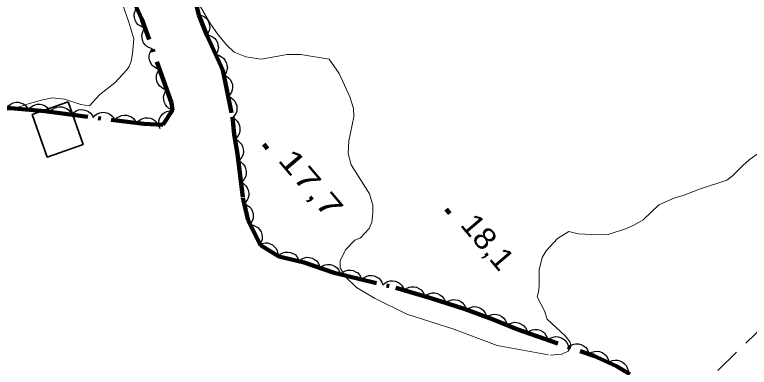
# Model space of a CAD drawing. Extents: x 386081 to 389416, y 5130568 to 5134082.
# Drawn here: x 387832.9 to 387934.2, y 5132350.3 to 5132398.8 of the extents above; entities that cross this region are included whole.
import ezdxf

# ---------------------------------------------------------------- set-up
doc = ezdxf.new("R2010")
doc.units = 0
doc.header["$LTSCALE"] = 1.2
for name, pattern in [('DOT_DASHED', [7.7, 5, -1.2, 0.3, -1.2]), ('LONG_DASHED', [7.5, 6, -1.5]), ('MEDIUM_DASHED', [4.5, 3, -1.5])]:
    doc.linetypes.add(name, pattern=pattern)
for name, color, linetype, lineweight in [('2', 7, 'Continuous', 13), ('21', 7, 'LONG_DASHED', 35), ('3', 7, 'Continuous', 140), ('31', 7, 'Continuous', 70), ('44', 7, 'Continuous', 25)]:
    doc.layers.add(name, color=color, linetype=linetype, lineweight=lineweight)

msp = doc.modelspace()

# ---------------------------------------------------------------- linework, layer by layer
at = {"layer": '2', "linetype": 'LONG_DASHED'}
for points in [[(387851.7, 5132416.27), (387848.9, 5132422.14), (387847.79, 5132425.35), (387846.86, 5132427.14), (387844.75, 5132429.85), (387843.63, 5132430.34), (387842.82, 5132429.9), (387842.32, 5132429.03), (387842.19, 5132427.54), (387842.37, 5132425.37), (387843.73, 5132419.43), (387845.59, 5132412.5), (387846.82, 5132404.45), (387847.74, 5132400.3), (387848.61, 5132397.83), (387849.29, 5132395.54), (387849.1, 5132393.49), (387848.91, 5132392.43), (387848.66, 5132391.69), (387848.35, 5132391.25)], [(387879.75, 5132367.77), (387878.5, 5132366.46), (387877.75, 5132364.96), (387877.75, 5132363.97), (387878.49, 5132362.74), (387879.98, 5132361.26), (387882.47, 5132359.8), (387886.95, 5132357.6), (387893.28, 5132355.56), (387899.37, 5132353.26), (387906.7, 5132351.96), (387908.32, 5132352.1), (387909.19, 5132352.48), (387909.56, 5132353.1), (387909.44, 5132353.72), (387908.82, 5132354.58), (387906.28, 5132356.91)]]:
    msp.add_lwpolyline(points, dxfattribs=at)
at = {"layer": '2'}
for points in [[(387879.75, 5132367.77), (387880.56, 5132368.09), (387881.74, 5132369.4), (387882.11, 5132370.27), (387882.24, 5132371.51), (387882.24, 5132372.63), (387881.81, 5132374.17), (387879.26, 5132378.18), (387878.83, 5132379.73), (387878.96, 5132381.46), (387879.65, 5132384.76), (387879.59, 5132385.93), (387879.09, 5132387.54), (387877.6, 5132390.75), (387876.24, 5132392.72), (387872.32, 5132393.37), (387870.45, 5132393.36), (387866.84, 5132392.71), (387864.73, 5132393.06), (387863.11, 5132393.67), (387862.12, 5132394.65), (387860.94, 5132396.07), (387859.76, 5132397.73), (387858.14, 5132400.57)], [(387848.35, 5132391.25), (387846.67, 5132389.44), (387844.61, 5132387.87), (387843.17, 5132386.31), (387841.99, 5132386.48), (387839.75, 5132387.21), (387838.06, 5132387.38), (387836.51, 5132387.06), (387834.45, 5132386.48), (387832.2, 5132385.72), (387831.14, 5132385.65), (387827.78, 5132386.61), (387823.73, 5132387.01), (387820.67, 5132387.05), (387817.8, 5132386.53), (387813.37, 5132385.43), (387809.87, 5132385.65), (387807.94, 5132385.95), (387805.94, 5132386.67), (387804.7, 5132387.41), (387803.14, 5132388.82), (387799.57, 5132393.79)], [(387936.17, 5132380.28), (387934.12, 5132378.84), (387933.25, 5132378.09), (387931.82, 5132376.65), (387931.07, 5132376.03), (387927.29, 5132374.82), (387925.05, 5132373.93), (387923.87, 5132373.61), (387921.7, 5132372.66), (387919.52, 5132370.6), (387918.34, 5132369.91), (387917.22, 5132369.4), (387914.68, 5132368.58), (387913.25, 5132368.5), (387910.58, 5132368.66), (387909.27, 5132368.96), (387907.72, 5132368.02), (387906.16, 5132366.33), (387905.6, 5132365.4), (387905.17, 5132363.72), (387905.16, 5132361.49), (387905.1, 5132360.68), (387904.91, 5132360), (387905.9, 5132358.03), (387906.28, 5132356.91)]]:
    msp.add_lwpolyline(points, dxfattribs=at)
at = {"layer": '21', "linetype": 'MEDIUM_DASHED'}
msp.add_lwpolyline([(387860.78, 5132286.44), (387862.78, 5132287.28), (387865.84, 5132288.2), (387868.86, 5132289.23), (387870.95, 5132290.29), (387873.09, 5132291.74), (387875.38, 5132293.66), (387881.62, 5132300.01), (387887.6, 5132305.78), (387894.9, 5132314.12), (387902.8, 5132322.8), (387912.7, 5132332.94), (387922.03, 5132342.34), (387944.62, 5132364.16), (387960.02, 5132379.36), (387967.89, 5132387.55), (387974.37, 5132394.99), (387979.87, 5132401.66), (387990.47, 5132414.87), (387993.62, 5132418.08), (388000.82, 5132427.01), (388006.82, 5132435.09), (388017.51, 5132449)], dxfattribs=at)
at = {"layer": '3'}
for p, q in [((387867.21, 5132381), (387867.72, 5132380.39)), ((387892.35, 5132372.08), (387892.86, 5132371.47))]:
    msp.add_line(p, q, dxfattribs=at)
at = {"layer": '31', "lineweight": 35}
msp.add_lwpolyline([(387840.24, 5132386.83), (387835.29, 5132385.09), (387837.34, 5132379.23), (387842.29, 5132380.96)], close=True, dxfattribs=at)
at = {"layer": '44', "linetype": 'DOT_DASHED', "lineweight": 90}
for points in [[(387831.29, 5132386.07), (387837.01, 5132385.55), (387850.69, 5132383.79), (387853.3, 5132383.66), (387854.61, 5132385.7), (387854.48, 5132386.7), (387850.42, 5132398.21), (387848.66, 5132402.09)], [(387857.55, 5132401.7), (387858.28, 5132398.8), (387859.37, 5132396.02), (387861.55, 5132391.19), (387862.88, 5132384.77), (387863.12, 5132382.35), (387863.6, 5132379.68), (387864.33, 5132373.63), (387865.06, 5132370.48), (387866.75, 5132367.1), (387869.29, 5132365.55), (387872.8, 5132364.73), (387876.92, 5132363.31), (387885.4, 5132361.21), (387890.24, 5132359.79), (387894.96, 5132358.26), (387898.83, 5132356.84), (387902.1, 5132355.54), (387912.71, 5132351.85), (387915.86, 5132350.42), (387917.67, 5132349.35)]]:
    msp.add_lwpolyline(points, dxfattribs=at)
at = {"layer": '44'}
for points in [[(387850.95, 5132397.03), (387850.54, 5132397.1), (387850.18, 5132397.29), (387849.91, 5132397.47), (387849.68, 5132397.74), (387849.5, 5132398.07), (387849.4, 5132398.44), (387849.35, 5132398.76), (387849.41, 5132399.11), (387849.53, 5132399.46), (387849.71, 5132399.77)], [(387858.26, 5132398.84), (387858.67, 5132398.75), (387859.02, 5132398.55), (387859.29, 5132398.35), (387859.49, 5132398.07), (387859.66, 5132397.74), (387859.74, 5132397.36), (387859.77, 5132397.04), (387859.7, 5132396.69), (387859.56, 5132396.35), (387859.36, 5132396.05)], [(387851.85, 5132394.16), (387851.44, 5132394.27), (387851.1, 5132394.48), (387850.84, 5132394.69), (387850.64, 5132394.98), (387850.49, 5132395.32), (387850.43, 5132395.69), (387850.4, 5132396.02), (387850.49, 5132396.36), (387850.64, 5132396.7), (387850.85, 5132396.99)], [(387859.36, 5132396.05), (387859.77, 5132395.98), (387860.13, 5132395.8), (387860.4, 5132395.61), (387860.63, 5132395.34), (387860.81, 5132395.02), (387860.9, 5132394.64), (387860.95, 5132394.32), (387860.9, 5132393.97), (387860.78, 5132393.62), (387860.59, 5132393.32)], [(387852.85, 5132391.33), (387852.44, 5132391.44), (387852.1, 5132391.65), (387851.84, 5132391.86), (387851.64, 5132392.15), (387851.49, 5132392.49), (387851.42, 5132392.86), (387851.4, 5132393.19), (387851.49, 5132393.53), (387851.63, 5132393.87), (387851.85, 5132394.16)], [(387860.59, 5132393.32), (387861, 5132393.25), (387861.37, 5132393.06), (387861.64, 5132392.88), (387861.86, 5132392.6), (387862.04, 5132392.28), (387862.14, 5132391.91), (387862.19, 5132391.59), (387862.13, 5132391.24), (387862.01, 5132390.89), (387861.82, 5132390.58)], [(387853.84, 5132388.5), (387853.44, 5132388.61), (387853.09, 5132388.82), (387852.84, 5132389.03), (387852.64, 5132389.32), (387852.49, 5132389.66), (387852.42, 5132390.04), (387852.4, 5132390.36), (387852.48, 5132390.7), (387852.63, 5132391.04), (387852.85, 5132391.33)], [(387861.69, 5132390.54), (387862.07, 5132390.38), (387862.39, 5132390.12), (387862.61, 5132389.88), (387862.77, 5132389.56), (387862.88, 5132389.21), (387862.89, 5132388.83), (387862.87, 5132388.5), (387862.74, 5132388.17), (387862.54, 5132387.86), (387862.29, 5132387.6)], [(387854.84, 5132385.67), (387854.44, 5132385.78), (387854.09, 5132385.99), (387853.84, 5132386.2), (387853.64, 5132386.49), (387853.48, 5132386.83), (387853.42, 5132387.21), (387853.4, 5132387.53), (387853.48, 5132387.87), (387853.63, 5132388.21), (387853.84, 5132388.5)], [(387862.29, 5132387.6), (387862.68, 5132387.44), (387862.99, 5132387.18), (387863.22, 5132386.94), (387863.38, 5132386.63), (387863.48, 5132386.27), (387863.5, 5132385.89), (387863.48, 5132385.56), (387863.34, 5132385.24), (387863.15, 5132384.92), (387862.9, 5132384.66)], [(387831.78, 5132386.03), (387832.05, 5132386.35), (387832.39, 5132386.57), (387832.68, 5132386.72), (387833.03, 5132386.78), (387833.4, 5132386.78), (387833.77, 5132386.68), (387834.07, 5132386.56), (387834.35, 5132386.34), (387834.6, 5132386.07), (387834.77, 5132385.75)], [(387834.77, 5132385.75), (387835.04, 5132386.08), (387835.37, 5132386.3), (387835.67, 5132386.45), (387836.02, 5132386.51), (387836.39, 5132386.51), (387836.76, 5132386.41), (387837.06, 5132386.29), (387837.34, 5132386.07), (387837.58, 5132385.8), (387837.76, 5132385.48)], [(387837.76, 5132385.45), (387838.03, 5132385.77), (387838.38, 5132385.98), (387838.68, 5132386.12), (387839.03, 5132386.16), (387839.4, 5132386.15), (387839.76, 5132386.03), (387840.06, 5132385.91), (387840.33, 5132385.68), (387840.57, 5132385.39), (387840.73, 5132385.07)], [(387840.73, 5132385.07), (387841.01, 5132385.38), (387841.35, 5132385.6), (387841.65, 5132385.73), (387842, 5132385.78), (387842.37, 5132385.76), (387842.74, 5132385.65), (387843.04, 5132385.52), (387843.31, 5132385.29), (387843.54, 5132385.01), (387843.71, 5132384.69)], [(387852.95, 5132383.11), (387852.78, 5132383.49), (387852.74, 5132383.9), (387852.74, 5132384.23), (387852.85, 5132384.56), (387853.02, 5132384.89), (387853.28, 5132385.17), (387853.53, 5132385.39), (387853.85, 5132385.53), (387854.21, 5132385.62), (387854.57, 5132385.63)], [(387843.71, 5132384.69), (387843.98, 5132385), (387844.33, 5132385.22), (387844.63, 5132385.35), (387844.98, 5132385.4), (387845.35, 5132385.38), (387845.71, 5132385.27), (387846.01, 5132385.14), (387846.28, 5132384.91), (387846.52, 5132384.63), (387846.68, 5132384.31)], [(387846.68, 5132384.31), (387846.96, 5132384.62), (387847.3, 5132384.83), (387847.61, 5132384.97), (387847.95, 5132385.01), (387848.32, 5132385), (387848.69, 5132384.89), (387848.99, 5132384.76), (387849.26, 5132384.53), (387849.49, 5132384.24), (387849.66, 5132383.92)], [(387849.65, 5132383.84), (387849.9, 5132384.18), (387850.23, 5132384.42), (387850.52, 5132384.57), (387850.86, 5132384.65), (387851.23, 5132384.66), (387851.61, 5132384.58), (387851.92, 5132384.47), (387852.2, 5132384.27), (387852.46, 5132384), (387852.65, 5132383.69)], [(387862.89, 5132384.66), (387863.26, 5132384.46), (387863.54, 5132384.17), (387863.74, 5132383.91), (387863.87, 5132383.58), (387863.93, 5132383.22), (387863.91, 5132382.83), (387863.85, 5132382.51), (387863.69, 5132382.2), (387863.46, 5132381.9), (387863.19, 5132381.67)], [(387863.24, 5132381.68), (387863.62, 5132381.51), (387863.93, 5132381.25), (387864.15, 5132381), (387864.3, 5132380.68), (387864.39, 5132380.32), (387864.4, 5132379.94), (387864.37, 5132379.62), (387864.23, 5132379.29), (387864.03, 5132378.98), (387863.77, 5132378.73)], [(387863.72, 5132378.72), (387864.09, 5132378.53), (387864.38, 5132378.25), (387864.58, 5132377.99), (387864.71, 5132377.66), (387864.79, 5132377.3), (387864.77, 5132376.92), (387864.72, 5132376.59), (387864.56, 5132376.28), (387864.35, 5132375.98), (387864.08, 5132375.74)], [(387864.08, 5132375.74), (387864.45, 5132375.55), (387864.74, 5132375.27), (387864.94, 5132375.01), (387865.07, 5132374.68), (387865.15, 5132374.32), (387865.13, 5132373.94), (387865.08, 5132373.62), (387864.92, 5132373.3), (387864.71, 5132373), (387864.43, 5132372.76)], [(387864.53, 5132372.78), (387864.92, 5132372.63), (387865.24, 5132372.38), (387865.47, 5132372.14), (387865.63, 5132371.83), (387865.75, 5132371.48), (387865.77, 5132371.1), (387865.76, 5132370.77), (387865.63, 5132370.44), (387865.45, 5132370.12), (387865.2, 5132369.86)], [(387865.35, 5132369.91), (387865.76, 5132369.85), (387866.13, 5132369.69), (387866.41, 5132369.51), (387866.64, 5132369.25), (387866.84, 5132368.93), (387866.95, 5132368.57), (387867.01, 5132368.24), (387866.97, 5132367.9), (387866.86, 5132367.54), (387866.69, 5132367.23)], [(387866.63, 5132367.17), (387867.01, 5132367.35), (387867.41, 5132367.4), (387867.74, 5132367.4), (387868.08, 5132367.3), (387868.41, 5132367.14), (387868.7, 5132366.88), (387868.92, 5132366.65), (387869.07, 5132366.33), (387869.17, 5132365.97), (387869.19, 5132365.61)], [(387869.18, 5132365.58), (387869.48, 5132365.86), (387869.85, 5132366.04), (387870.16, 5132366.14), (387870.52, 5132366.15), (387870.88, 5132366.1), (387871.23, 5132365.95), (387871.52, 5132365.79), (387871.76, 5132365.54), (387871.97, 5132365.23), (387872.1, 5132364.89)], [(387872.12, 5132364.96), (387872.45, 5132365.22), (387872.84, 5132365.35), (387873.16, 5132365.43), (387873.51, 5132365.4), (387873.87, 5132365.31), (387874.2, 5132365.13), (387874.47, 5132364.94), (387874.69, 5132364.66), (387874.86, 5132364.33), (387874.96, 5132363.99)], [(387874.96, 5132363.99), (387875.29, 5132364.24), (387875.67, 5132364.38), (387875.99, 5132364.45), (387876.35, 5132364.42), (387876.7, 5132364.33), (387877.04, 5132364.15), (387877.31, 5132363.96), (387877.52, 5132363.68), (387877.7, 5132363.36), (387877.79, 5132363.01)], [(387877.81, 5132363.09), (387878.13, 5132363.37), (387878.49, 5132363.54), (387878.81, 5132363.64), (387879.16, 5132363.65), (387879.53, 5132363.59), (387879.88, 5132363.43), (387880.16, 5132363.27), (387880.4, 5132363.02), (387880.6, 5132362.71), (387880.73, 5132362.37)], [(387880.73, 5132362.37), (387881.04, 5132362.65), (387881.41, 5132362.82), (387881.72, 5132362.92), (387882.07, 5132362.92), (387882.44, 5132362.87), (387882.79, 5132362.71), (387883.07, 5132362.55), (387883.31, 5132362.29), (387883.51, 5132361.98), (387883.64, 5132361.65)], [(387883.64, 5132361.65), (387883.95, 5132361.93), (387884.32, 5132362.1), (387884.63, 5132362.2), (387884.98, 5132362.2), (387885.35, 5132362.15), (387885.7, 5132361.99), (387885.98, 5132361.83), (387886.22, 5132361.57), (387886.43, 5132361.26), (387886.55, 5132360.92)], [(387886.54, 5132360.88), (387886.86, 5132361.14), (387887.24, 5132361.3), (387887.55, 5132361.38), (387887.91, 5132361.38), (387888.27, 5132361.3), (387888.61, 5132361.13), (387888.89, 5132360.96), (387889.12, 5132360.69), (387889.31, 5132360.37), (387889.42, 5132360.03)], [(387889.42, 5132360.05), (387889.75, 5132360.31), (387890.13, 5132360.46), (387890.45, 5132360.53), (387890.8, 5132360.52), (387891.16, 5132360.43), (387891.5, 5132360.25), (387891.78, 5132360.07), (387892, 5132359.8), (387892.18, 5132359.48), (387892.28, 5132359.13)], [(387892.28, 5132359.13), (387892.61, 5132359.39), (387892.99, 5132359.53), (387893.31, 5132359.61), (387893.66, 5132359.59), (387894.02, 5132359.51), (387894.36, 5132359.33), (387894.63, 5132359.15), (387894.85, 5132358.87), (387895.03, 5132358.55), (387895.13, 5132358.2)], [(387895.13, 5132358.2), (387895.47, 5132358.44), (387895.85, 5132358.57), (387896.18, 5132358.64), (387896.53, 5132358.61), (387896.88, 5132358.51), (387897.22, 5132358.32), (387897.48, 5132358.13), (387897.69, 5132357.84), (387897.86, 5132357.51), (387897.95, 5132357.16)], [(387897.95, 5132357.19), (387898.3, 5132357.42), (387898.69, 5132357.54), (387899.01, 5132357.6), (387899.36, 5132357.56), (387899.72, 5132357.45), (387900.04, 5132357.25), (387900.3, 5132357.05), (387900.5, 5132356.77), (387900.66, 5132356.43), (387900.74, 5132356.08)], [(387900.72, 5132356.02), (387901.05, 5132356.27), (387901.44, 5132356.41), (387901.76, 5132356.48), (387902.11, 5132356.45), (387902.47, 5132356.36), (387902.8, 5132356.18), (387903.07, 5132355.99), (387903.29, 5132355.71), (387903.46, 5132355.38), (387903.55, 5132355.03)], [(387903.55, 5132355.03), (387903.89, 5132355.28), (387904.27, 5132355.42), (387904.59, 5132355.49), (387904.94, 5132355.47), (387905.3, 5132355.37), (387905.64, 5132355.19), (387905.91, 5132355), (387906.12, 5132354.72), (387906.29, 5132354.4), (387906.39, 5132354.05)], [(387906.39, 5132354.05), (387906.72, 5132354.3), (387907.1, 5132354.44), (387907.43, 5132354.51), (387907.78, 5132354.48), (387908.14, 5132354.39), (387908.47, 5132354.2), (387908.74, 5132354.02), (387908.95, 5132353.74), (387909.13, 5132353.41), (387909.22, 5132353.06)], [(387909.22, 5132353.06), (387909.56, 5132353.31), (387909.94, 5132353.45), (387910.26, 5132353.52), (387910.61, 5132353.49), (387910.97, 5132353.4), (387911.31, 5132353.22), (387911.57, 5132353.03), (387911.79, 5132352.75), (387911.96, 5132352.43), (387912.05, 5132352.08)], [(387912.08, 5132352.14), (387912.43, 5132352.36), (387912.83, 5132352.46), (387913.16, 5132352.5), (387913.5, 5132352.44), (387913.85, 5132352.32), (387914.17, 5132352.1), (387914.42, 5132351.89), (387914.61, 5132351.59), (387914.75, 5132351.25), (387914.81, 5132350.9)], [(387914.87, 5132351.01), (387915.24, 5132351.19), (387915.65, 5132351.25), (387915.98, 5132351.25), (387916.32, 5132351.15), (387916.65, 5132350.99), (387916.94, 5132350.75), (387917.17, 5132350.51), (387917.32, 5132350.2), (387917.43, 5132349.84), (387917.45, 5132349.48)]]:
    msp.add_lwpolyline(points, dxfattribs=at)

# ---------------------------------------------------------------- texts
at = {"layer": '3'}
for s, width, p in [('17,7   ', 1.4, (387869.04, 5132378.78)), ('18,1   ', 1.1, (387894.18, 5132369.86))]:
    msp.add_text(s, height=3, rotation=310.294, dxfattribs=dict(at, width=width)).set_placement(p)

doc.saveas('drawing.dxf')
